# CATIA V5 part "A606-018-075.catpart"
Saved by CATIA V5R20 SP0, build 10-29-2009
Part number: A606-018-075
Source: Unknown
Property "ARTICLENO": "A606-018-075"
Property "BOMINFO": "A606-018-075"
Property "CODE": "A606-018-075"
Property "HOLES": "2"
Property "L": "75.000"
Property "L1": "15.000"
Property "L2": "45.000"
Property "LINA": "A606-018-075"
Property "NB": "A606-018-075"
Property "NBSYN": "$CODE."
Property "NN": "A606"
Property "NT": "Wear Plates, self-lubricating"
Property "SCREW": "2xM6"
Property "SUPPLIER": "CF"
Property "W": "18.000"
Bounding box of the stored display mesh (mm): x -9 to 9, y -5 to 5, z -37.5 to 37.5
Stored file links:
  C:\Users\Utente\Desktop\3D files A606\A606-018-075.catpart
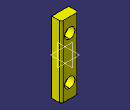
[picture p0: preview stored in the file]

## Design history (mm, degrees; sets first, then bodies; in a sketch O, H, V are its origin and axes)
Body1 "Geometry.1" (main body)
  Solid1 "A606-018-075.catpart": solid without history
